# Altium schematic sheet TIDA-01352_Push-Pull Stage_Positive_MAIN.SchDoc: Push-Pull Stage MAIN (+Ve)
size 431 x 279 mm; Date: Not shown in title block; ApprovedBy: Not shown in title block; CheckedBy: Not shown in title block; Author: Not shown in title block; CompanyName: Not shown in title block; DrawnBy: Sanjay Pithadia; Engineer: Sanjay Pithadia; Organization: Not shown in title block; Address1: Not shown in title block; Address2: Not shown in title block; Address3: Not shown in title block; Address4: Not shown in title block; DocumentNumber: 1; Revision: Use project parameter SCH_Rev; SheetNumber: 2; SheetTotal: 9; PageSetup: Record=PageOptions¦CenterHorizontal=True¦CenterVertical=True¦PrintScale=1.00¦XCorrection=1.00¦YCorrection=1.00¦PrintKind=0¦BorderSize=5000000¦LeftOffset=0¦BottomOffset=0¦Orientation=2¦PaperLength=1000¦PaperWidth=1000¦Scale=100¦PaperSource=15¦PrintQuality=600¦MediaType=1¦DitherType=10¦PaperKind=Letter¦PrintScaleMode=1
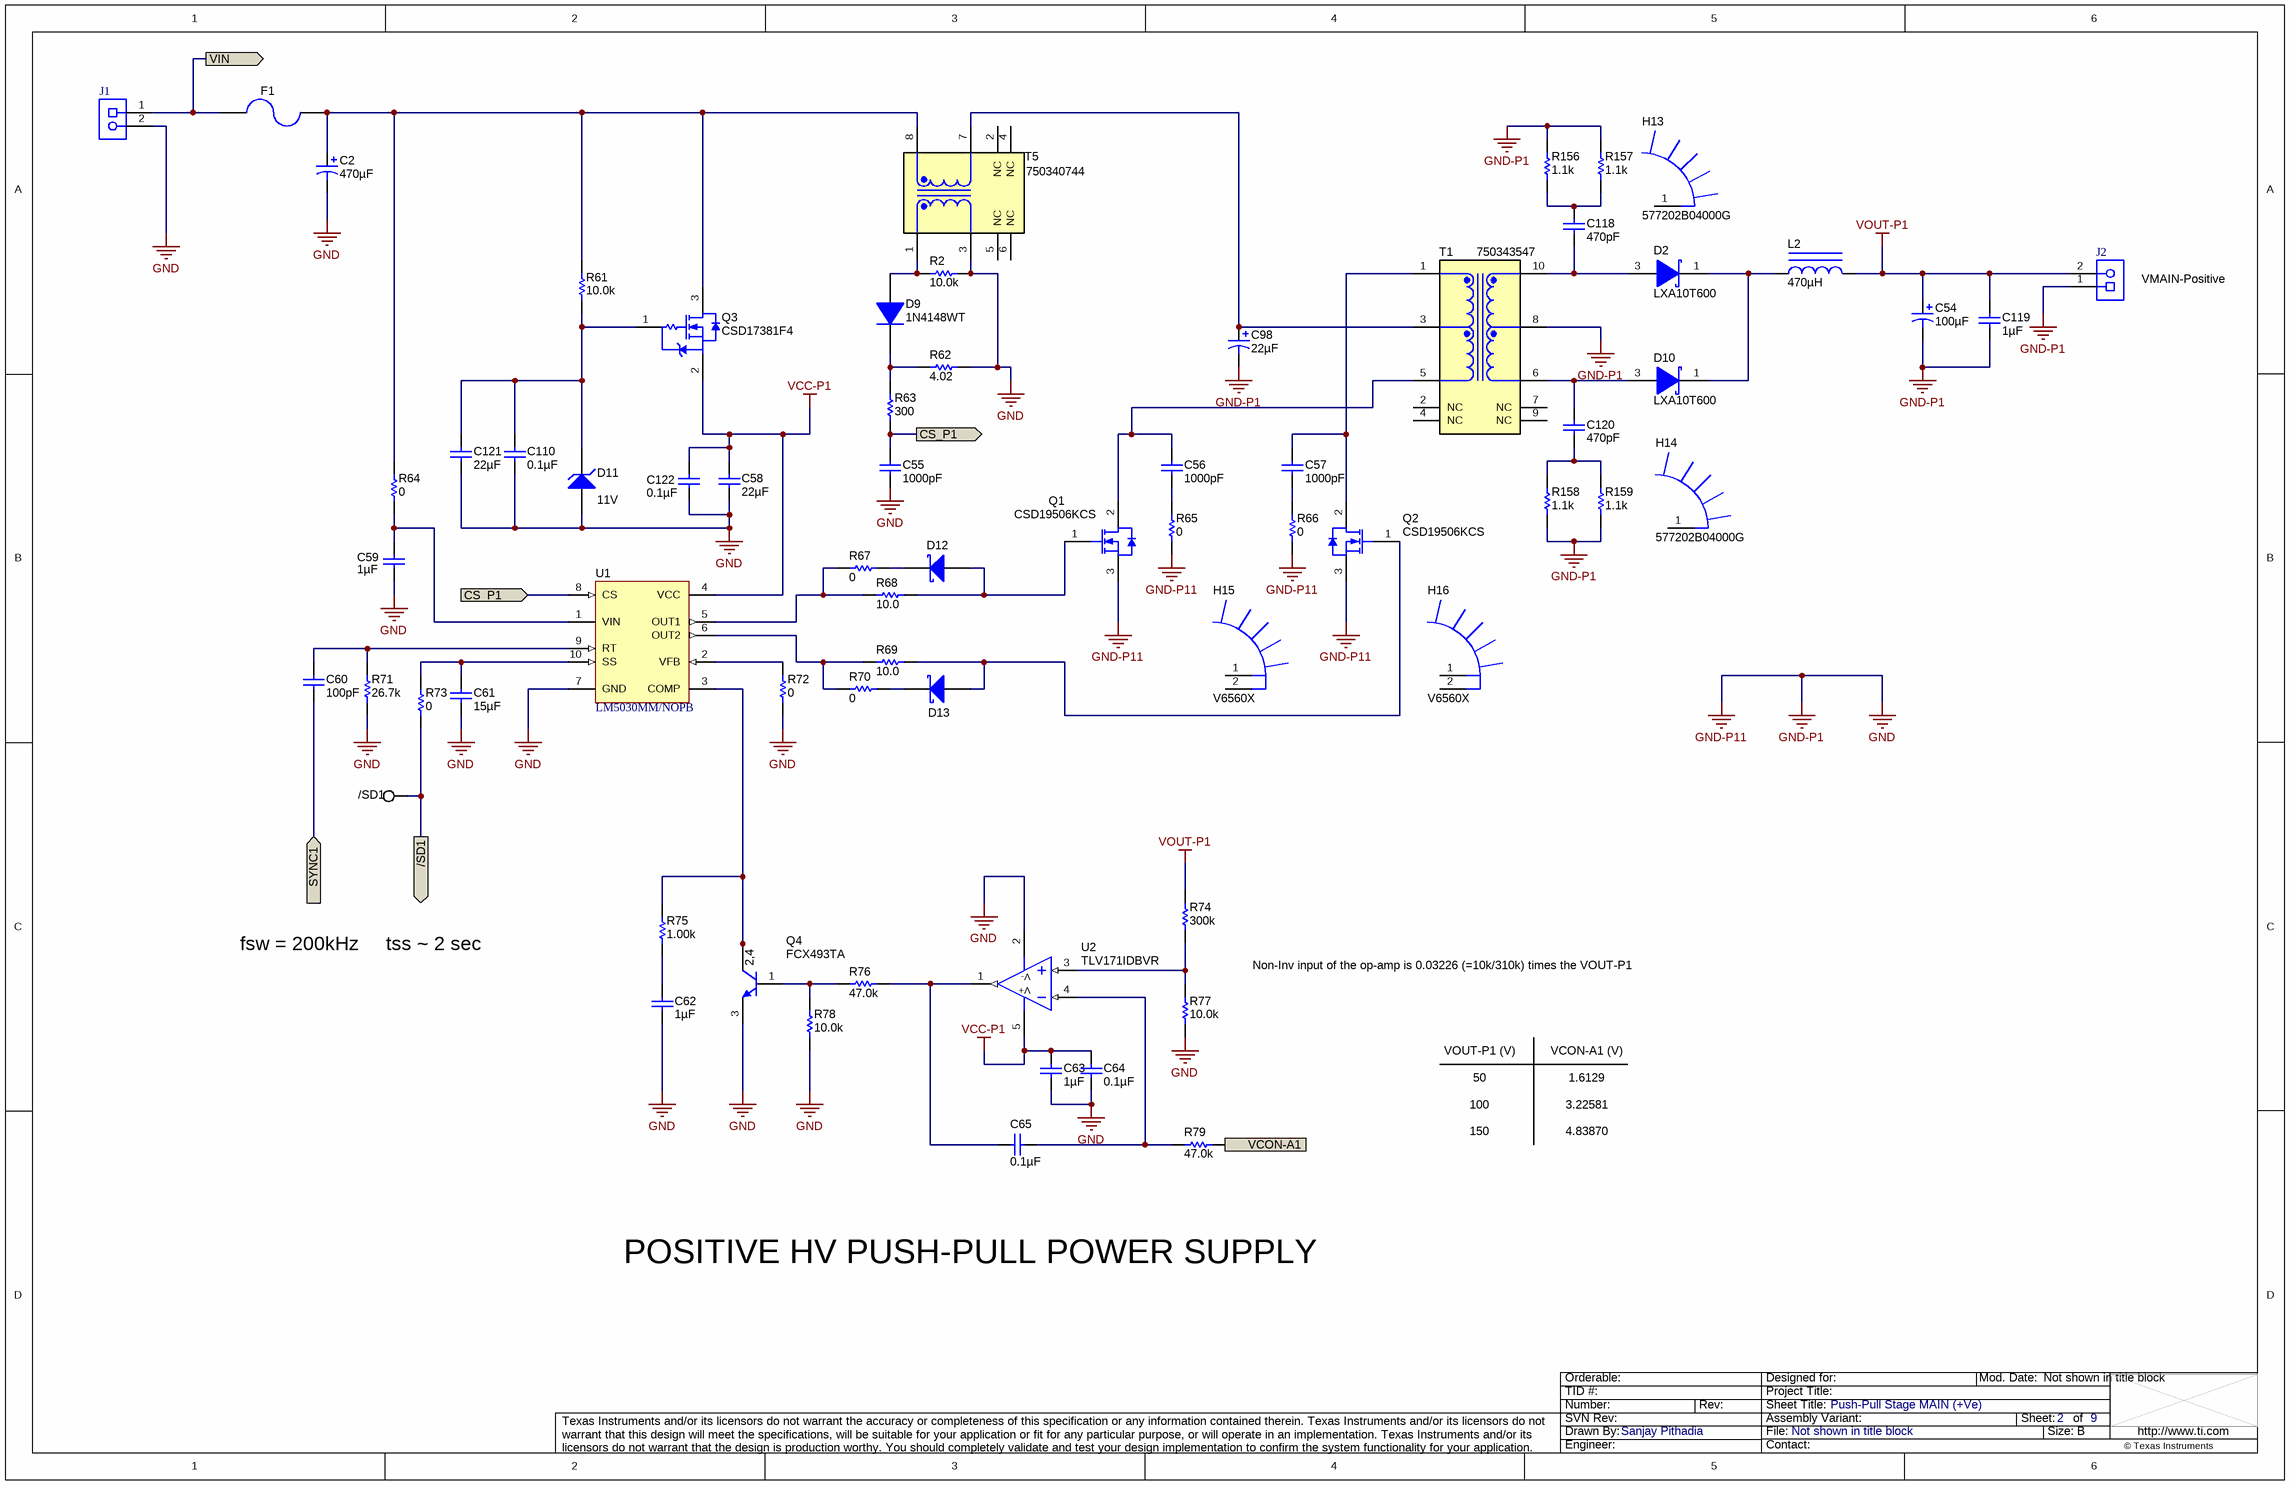
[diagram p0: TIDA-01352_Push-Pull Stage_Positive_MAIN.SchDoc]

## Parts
/SD1  5002  [Keystone5002]  (value not drawn)
C2  ValueDisplayed: 470µF  [WCAP-ATLI_1300x3000]  (hidden comment: 860080778023)
C54  ValueDisplayed: 100µF  [Nichicon_2000x3000_Snap]  (hidden comment: LLS2G101MELY)
C55  ValueDisplayed: 1000pF  [0603]  (hidden comment: GRM188R71E102KA01D)
C56  ValueDisplayed: 1000pF  [0603]  (hidden comment: GRM188R71E102KA01D)
C57  ValueDisplayed: 1000pF  [0603]  (hidden comment: GRM188R71E102KA01D)
C58  ValueDisplayed: 22µF  [1210_280]  (hidden comment: 12103D226MAT2A)
C59  ValueDisplayed: 1µF  [0805_HV]  (hidden comment: 08055C105KAT2A)
C60  ValueDisplayed: 100pF  [0603]  (hidden comment: 06035A101FAT2A)
C61  ValueDisplayed: 15µF  [0805_HV]  (hidden comment: C2012X5R1V156M125AC)
C62  ValueDisplayed: 1µF  [0603]  (hidden comment: GMK107BJ105KA-T)
C63  ValueDisplayed: 1µF  [0805_HV]  (hidden comment: 08055C105KAT2A)
C64  ValueDisplayed: 0.1µF  [0603]  (hidden comment: 06035C104KAT2A)
C65  ValueDisplayed: 0.1µF  [0603]  (hidden comment: 06035C104KAT2A)
C98  ValueDisplayed: 22µF  [SM_RADIAL_E]  (hidden comment: EEE-FC1H220P)
C110  ValueDisplayed: 0.1µF  [0603]  (hidden comment: 06035C104KAT2A)
C118  ValueDisplayed: 470pF  [1206]  (hidden comment: VJ1206Y471KBEAT4X)
C119  ValueDisplayed: 1µF  [2220_200]  (hidden comment: GRM55DR72E105KW01L)
C120  ValueDisplayed: 470pF  [1206]  (hidden comment: VJ1206Y471KBEAT4X)
C121  ValueDisplayed: 22µF  [1210_280]  (hidden comment: 12103D226MAT2A)
C122  ValueDisplayed: 0.1µF  [0603]  (hidden comment: 06035C104KAT2A)
D2  LXA10T600  [TO-220AC]
D9  1N4148WT  [Fairchild_SOD-523F]
D10  LXA10T600  [TO-220AC]
D11  value 11V  [SMA]  (hidden comment: 1SMA5926BT3G)
D12  PMEG1030EJ,115  [SOD-323F]  (value not drawn)
D13  PMEG1030EJ,115  [SOD-323F]  (value not drawn)
F1  0678L9150-02  [Fuse_0678L]  (value not drawn)
H13  577202B04000G  [Aavid_577202B04000G]
H14  577202B04000G  [Aavid_577202B04000G]
H15  V6560X  [ASMN_V6560X]
H16  V6560X  [ASMN_V6560X]
J1  OSTT7020150  [On-Shore_OSTT7020150]  (value not drawn)
J2  1727010  [PhoenixConact_1727010]  (value not drawn)
L2  ValueDisplayed: 470µH  [1447440C]  (hidden comment: 1447440C)
Q1  CSD19506KCS  [KCS0003B]
Q2  CSD19506KCS  [KCS0003B]
Q3  CSD17381F4  [YJC0003A]
Q4  FCX493TA  [SOT-89-3]
R2  ValueDisplayed: 10.0k  [0603]  (hidden comment: CRCW060310K0FKEA)
R61  ValueDisplayed: 10.0k  [0603]  (hidden comment: CRCW060310K0FKEA)
R62  ValueDisplayed: 4.02  [0805_HV]  (hidden comment: CRCW08054R02FKEA)
R63  ValueDisplayed: 300  [0603]  (hidden comment: RC0603FR-07300RL)
R64  ValueDisplayed: 0  [0603]  (hidden comment: CRCW06030000Z0EA)
R65  ValueDisplayed: 0  [0603]  (hidden comment: CRCW06030000Z0EA)
R66  ValueDisplayed: 0  [0603]  (hidden comment: CRCW06030000Z0EA)
R67  ValueDisplayed: 0  [0603]  (hidden comment: CRCW06030000Z0EA)
R68  ValueDisplayed: 10.0  [0603]  (hidden comment: CRCW060310R0FKEA)
R69  ValueDisplayed: 10.0  [0603]  (hidden comment: CRCW060310R0FKEA)
R70  ValueDisplayed: 0  [0603]  (hidden comment: CRCW06030000Z0EA)
R71  ValueDisplayed: 26.7k  [0603]  (hidden comment: CRCW060326K7FKEA)
R72  ValueDisplayed: 0  [0603]  (hidden comment: CRCW06030000Z0EA)
R73  ValueDisplayed: 0  [0603]  (hidden comment: CRCW06030000Z0EA)
R74  ValueDisplayed: 300k  [1206]  (hidden comment: RC1206FR-07300KL)
R75  ValueDisplayed: 1.00k  [0603]  (hidden comment: CRCW06031K00FKEA)
R76  ValueDisplayed: 47.0k  [0603]  (hidden comment: RC0603FR-0747KL)
R77  ValueDisplayed: 10.0k  [1206]  (hidden comment: CRCW120610K0FKEA)
R78  ValueDisplayed: 10.0k  [0603]  (hidden comment: CRCW060310K0FKEA)
R79  ValueDisplayed: 47.0k  [0603]  (hidden comment: RC0603FR-0747KL)
R156  ValueDisplayed: 1.1k  [PR01]  (hidden comment: PR01000101101JR500)
R157  ValueDisplayed: 1.1k  [PR01]  (hidden comment: PR01000101101JR500)
R158  ValueDisplayed: 1.1k  [PR01]  (hidden comment: PR01000101101JR500)
R159  ValueDisplayed: 1.1k  [PR01]  (hidden comment: PR01000101101JR500)
T1  750343547  [Wurth_750343473]
T5  750340744  [Wurth_750340744]
U1  LM5030MM/NOPB  [MUB10A_N]
U2  TLV171IDBVR  [DBV0005A_N]

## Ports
/SD1 (out), CS_P1 (in), CS_P1 (out), SYNC1 (in), VCON-A1 (in), VIN (out)

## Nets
GND: C2.2(-) C54.2(-) C55.2 C58.2 C59.2 C61.2 C62.2 C63.2 C64.2 C98.2(-) C110.2 C119.2 C121.2 C122.2 D11.2(A) J1.2 J2.1 Q1.3(S) Q2.3(S) Q4.3(E) R2.1 R62.2 R65.2 R66.2 R71.1 R72.1 R77.1 R78.1 R156.2 R157.2 R158.1 R159.1 T1.8 T5.3 U1.7(GND) U2.2(V-)  [also labelled GND-P1, GND-P11]
VCC-P1: C58.1 C63.1 C64.1 C122.1 Q3.2(S) U1.4(VCC) U2.5(V+)
VOUT-P1: C54.1(+) C119.1 J2.2 L2.2 R74.2
/SD1: /SD1.1 R73.1 ; port /SD1
CS_P1: C55.1 R63.1 U1.8(CS) ; port CS_P1
SYNC1: C60.2 ; port SYNC1
VCON-A1: R79.2 ; port VCON-A1
VIN: F1.2 J1.1 ; port VIN
NetC2_1: C2.1(+) F1.1 Q3.3(D) R61.2 R64.2 T5.8
NetC56_1: C56.1 Q1.2(D) T1.5
NetC56_2: C56.2 R65.1
NetC57_1: C57.1 Q2.2(D) T1.1
NetC57_2: C57.2 R66.1
NetC59_1: C59.1 R64.1 U1.1(VIN)
NetC60_1: C60.1 R71.2 U1.9(RT)
NetC61_1: C61.1 R73.2 U1.10(SS)
NetC62_1: C62.1 R75.1
NetC65_1: C65.1 R79.1 U2.4(IN-)
NetC65_2: C65.2 R76.2 U2.1(OUT)
NetC98_1: C98.1(+) T1.3 T5.7
NetC110_1: C110.1 C121.1 D11.1(K) Q3.1(G) R61.1
NetC118_1: C118.1 R156.1 R157.1
NetC118_2: C118.2 D2.3(K) T1.10
NetC120_1: C120.1 D10.3(K) T1.6
NetC120_2: C120.2 R158.2 R159.2
NetD2_1: D2.1(A) D10.1(A) L2.1
NetD9_1: D9.1(K) R62.1 R63.2
NetD9_2: D9.2(A) R2.2 T5.1
NetD12_1: D12.1(K) R67.1
NetD12_2: D12.2(A) Q1.1(G) R68.2
NetD13_1: D13.1(K) R70.1
NetD13_2: D13.2(A) Q2.1(G) R69.2
NetQ4_1: Q4.1(B) R76.1 R78.2
NetQ4_2: Q4.2(C) Q4.4(C) R75.2 U1.3(COMP)
NetR67_2: R67.2 R68.1 U1.5(OUT1)
NetR69_1: R69.1 R70.2 U1.6(OUT2)
NetR72_2: R72.2 U1.2(VFB)
NetR74_1: R74.1 R77.2 U2.3(IN+)

Not connected (* = marked no-connect by the designer): H13 1; H14 1; H15 1 2; H16 1 2; T1 2(NC) 4(NC) 7(NC) 9(NC); T5 2(NC) 4(NC) 5(NC) 6(NC)

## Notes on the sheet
- (near J2) VMAIN-Positive
- fsw = 200kHz
- tss ~ 2 sec
- Non-Inv input of the op-amp is 0.03226 (=10k/310k) times the VOUT-P1
- VOUT-P1 (V)
- 50
- 100
- VCON-A1 (V)
- 1.6129
- 3.22581
- 150
- 4.83870
- POSITIVE HV PUSH-PULL POWER SUPPLY

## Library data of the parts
/SD1 = 5002: Test Point, Miniature, White, TH; Manufacturer: Keystone; CompType: Test Point Loop; ContactFinish: Silver
C2 = 860080778023: CAP, AL, 470 µF, 63 V, +/- 20%, TH; Manufacturer: Wurth Elektronik; Polarized: Y; CompType: Capacitor; Value: 470uF; U/M: EA; Cap_F: 0.00047; Tolerance_%: 20; Value1: Unknown; VDC_V: 63; Value2: 63V; IRMS_A: 2.225; TaMin_C: -55; TaMax_C: 105; Cap_Case: 13x30mm; SizeAreaWB_mm2: 225; SizeArea_mm2: 169; SizeX_mm: 13; SizeZ_mm: 31.5; AEC Category: Q200; AEC Qualified: N
C54 = LLS2G101MELY: CAP, AL, 100 µF, 400 V, +/- 20%, TH; Manufacturer: Nichicon; Polarized: Y; CompType: Capacitor; Value: 100uF; U/M: EA; Cap_F: 0.0001; Tolerance_%: 20; Value1: Unknown; VDC_V: 400; Value2: 400V; IRMS_A: 0.95; TaMin_C: -25; TaMax_C: 85; Cap_Case: 20x30mm; SizeAreaWB_mm2: 484; SizeZ_mm: 32; AEC Category: Q200; AEC Qualified: N
C55-C57 = GRM188R71E102KA01D: CAP, CERM, 1000 pF, 25 V, +/- 10%, X7R, 0603; Manufacturer: MuRata; Polarized: N; CompType: Capacitor; Value: 1000pF; U/M: EA; Cap_F: 0.000000001; Tolerance_%: 10; Value1: Unknown; VDC_V: 25; Value2: 25V; TaMin_C: -55; TaMax_C: 125; SizeArea_mm2: 1.28; SizeAreaWB_mm2: 4.68; SizeX_mm: 1.6; SizeY_mm: 0.8; SizeZ_mm: 1; AEC Category: Q200
C58 C121 = 12103D226MAT2A: CAP, CERM, 22 µF, 25 V, +/- 20%, X5R, 1210; Manufacturer: AVX; Polarized: N; CompType: Capacitor; Value: 22uF; U/M: EA; Cap_F: 0.000022; Tolerance_%: 20; Value1: Unknown; VDC_V: 25; Value2: 25V; TaMin_C: -55; TaMax_C: 85; Cap_Case: 1210; SizeArea_mm2: 8; SizeAreaWB_mm2: 14.7; SizeX_mm: 3.2; SizeY_mm: 2.5; SizeZ_mm: 2.8; AEC Category: Q200
C59 C63 = 08055C105KAT2A: CAP, CERM, 1 µF, 50 V, +/- 10%, X7R, 0805; Manufacturer: AVX; Polarized: N; CompType: Capacitor; Value: 1uF; U/M: EA; Cap_F: 0.000001; Tolerance_%: 10; Value1: Unknown; VDC_V: 50; Value2: 50V; TaMin_C: -55; TaMax_C: 125; Cap_Case: 0805; SizeArea_mm2: 2.5; SizeAreaWB_mm2: 6.75; SizeX_mm: 2; SizeY_mm: 1.25; SizeZ_mm: 1.45; AEC Category: Q200
C60 = 06035A101FAT2A: CAP, CERM, 100 pF, 50 V, +/- 1%, C0G/NP0, 0603; Manufacturer: AVX; Polarized: N; CompType: Capacitor; Value: 100pF; U/M: EA; Cap_F: 0.0000000001; Tolerance_%: 1; Value1: Unknown; VDC_V: 50; Value2: 50V; TaMin_C: -55; TaMax_C: 125; SizeArea_mm2: 1.28; SizeAreaWB_mm2: 4.68; SizeX_mm: 1.6; SizeY_mm: 0.8; AEC Category: Q200
C61 = C2012X5R1V156M125AC: CAP, CERM, 15 µF, 35 V, +/- 20%, X5R, 0805; Manufacturer: TDK; Polarized: N; CompType: Capacitor; Value: 15uF; U/M: EA; Cap_F: 0.000015; Tolerance_%: 20; ESR_ohm: 0.001669; Value1: 0.001669 ohm; VDC_V: 35; Value2: 35V; IRMS_A: 5.04984; TaMin_C: -55; TaMax_C: 85; Cap_Case: 0805; SizeArea_mm2: 2.5; SizeAreaWB_mm2: 6.75; SizeX_mm: 2; SizeY_mm: 1.25; SizeZ_mm: 1.45; AEC Category: Q200
C62 = GMK107BJ105KA-T: CAP, CERM, 1 µF, 35 V, +/- 10%, X5R, 0603; Manufacturer: Taiyo Yuden; Polarized: N; CompType: Capacitor; Value: 1uF; U/M: EA; Cap_F: 0.000001; Tolerance_%: 10; Value1: Unknown; VDC_V: 35; Value2: 35V; TaMin_C: -55; TaMax_C: 85; SizeArea_mm2: 1.28; SizeAreaWB_mm2: 4.68; SizeX_mm: 1.6; SizeY_mm: 0.8; SizeZ_mm: 1; AEC Category: Q200
C64 C65 C110 C122 = 06035C104KAT2A: CAP, CERM, 0.1 µF, 50 V, +/- 10%, X7R, 0603; Manufacturer: AVX; Polarized: N; CompType: Capacitor; Value: 0.1uF; U/M: EA; Cap_F: 0.0000001; Tolerance_%: 10; Value1: Unknown; VDC_V: 50; Value2: 50V; TaMin_C: -55; TaMax_C: 125; SizeArea_mm2: 1.28; SizeAreaWB_mm2: 4.68; SizeX_mm: 1.6; SizeY_mm: 0.8; SizeZ_mm: 1; AEC Category: Q200
C98 = EEE-FC1H220P: CAP, AL, 22 µF, 50 V, +/- 20%, 0.7 ohm, SMD; Manufacturer: Panasonic; Polarized: Y; CompType: Capacitor; Value: 22uF; U/M: EA; Cap_F: 0.000022; Tolerance_%: 20; Value1: 0.7 ohm; VDC_V: 50; Value2: 50V; ESR_ohm: 0.7; IRMS_A: 0.12; TaMin_C: -40; TaMax_C: 105; Cap_Case: E; SizeAreaWB_mm2: 118.45; SizeArea_mm2: 78.85; SizeX_mm: 9.5; SizeY_mm: 8.3; SizeZ_mm: 6.2; AEC Category: Q200
C118 C120 = VJ1206Y471KBEAT4X: CAP, CERM, 470 pF, 500 V, +/- 10%, X7R, 1206; Manufacturer: Vishay-Vitramon; Polarized: N; CompType: Capacitor; Value: 470pF; U/M: EA; Cap_F: 0.00000000047; Tolerance_%: 10; Value1: Unknown; VDC_V: 500; Value2: 500V; TaMin_C: -55; TaMax_C: 125; SizeArea_mm2: 5.12; SizeAreaWB_mm2: 10.92; SizeX_mm: 3.2; SizeY_mm: 1.6; SizeZ_mm: 1.35; AEC Category: Q200
C119 = GRM55DR72E105KW01L: CAP, CERM, 1 µF, 250 V, +/- 10%, X7R, 2220; Manufacturer: MuRata; Polarized: N; CompType: Capacitor; Value: 1uF; U/M: EA; Cap_F: 0.000001; Tolerance_%: 10; ESR_ohm: 0.007086; Value1: 0.007086 ohm; VDC_V: 250; Value2: 250V; IRMS_A: 2.0605; TaMin_C: -55; TaMax_C: 125; Cap_Case: 2220; SizeArea_mm2: 28.5; SizeAreaWB_mm2: 53.9; SizeX_mm: 5.7; SizeY_mm: 5; SizeZ_mm: 2; AEC Category: Q200
D2 D10 = LXA10T600: Diode, Schottky, 600 V, 10 A, TH; Manufacturer: Power Integrations; SymbolCreator: a0412235; U/M: EA; Vf_V: 2.4; Value: 600V; Value1: 10A; Value2: 2.4V; Io_A: 10; Vr_V: 600; TJmax_C: 150; RJC_CperW: 1.4; SizeAreaWB_mm2: 78.975; SizeArea_mm2: 45.675; SizeX_mm: 10.15; SizeY_mm: 4.5; SizeZ_mm: 23; AEC Category: Q101; AEC Qualified: N
D9 = 1N4148WT: Diode, Switching, 75 V, 0.3 A, SOD-523F; Manufacturer: Fairchild Semiconductor; U/M: EA; Value: 75V; Value1: 0.3A; Io_A: 0.3; Vr_V: 75; TJmax_C: 150; SizeAreaWB_mm2: 4.68; SizeArea_mm2: 1.28; SizeX_mm: 1.6; SizeY_mm: 0.8; SizeZ_mm: 0.7; AEC Category: Q101
D11 = 1SMA5926BT3G: Diode, Zener, 11 V, 1.5 W, SMA; Manufacturer: ON Semiconductor; SymbolCreator: a0412235; U/M: EA; Power_W: 1.5; Vz_V: 11; Value1: 1.5W; RJA_CperW: 250; SizeAreaWB_mm2: 37.3428; SizeArea_mm2: 16.3228; SizeX_mm: 5.59; SizeY_mm: 2.92; SizeZ_mm: 2.87; AEC Category: Q101
D12 D13 = PMEG1030EJ,115: Diode, Schottky, 10 V, 3 A, SOD-323F; Manufacturer: NXP Semiconductor; U/M: EA; Vf_V: 0.53; Value: 10V; Value1: 3A; Value2: 0.53V; Io_A: 3; Vr_V: 10; TJmax_C: 150; SizeAreaWB_mm2: 7.875; SizeArea_mm2: 3.125; SizeX_mm: 2.5; SizeY_mm: 1.25; SizeZ_mm: 0.8; AEC Category: Q101; AEC Qualified: N
F1 = 0678L9150-02: Fuse, 15 A, 250 VAC, 72 VDC, SMD; Manufacturer: Bel Fuse; SizeAreaWB_mm2: 59.59; SizeArea_mm2: 29.89; SizeX_mm: 9.8; SizeY_mm: 3.05; SizeZ_mm: 3.18; VDC_V: 72; VAC_V: 250; Irating_A: 15; Rtyp_Ohm: 0.0036; MeltingTyp: 110
H13 H14 = 577202B04000G: HEATSINK TO-220 .500" COMPACT; Manufacturer: Aavid; SymbolCreator: a0412235
H15 H16 = V6560X: HEATSINK, ALUM, ANOD, for TO-220; Manufacturer: Assman WSW; SymbolCreator: a0799628
J1 = OSTT7020150: Terminal Block, 6.35mm, 2x1, TH; Manufacturer: On-Shore Technology; SymbolCreator: a0412235; Pitch_mm: 6.35; Gender: Female; Row_Count: 1; Current_A: 30; Voltage_V: 300; Cert_UL: Y
J2 = 1727010: Conn Term Block, 2POS, 3.81mm, TH; Manufacturer: Phoenix Contact; SymbolCreator: a0412235; CompType: Terminal Block
L2 = 1447440C: Inductor, Wirewound, 470 µH, 4 A, 0.125 ohm, TH; Manufacturer: MuRata; Value: 470uH; Ind_H: 470.0E-6; Imax_A: 4; Irms: 4A @ 50C rise; Isat: 4A @ 40% inductance drop; DCR_ohm: 0.125; Value2: 4A; SizeAreaWB_mm2: 1071.66; SizeArea_mm2: 944.66; SizeX_mm: 31.7; SizeY_mm: 29.8; SizeZ_mm: 23.5; AEC Category: Q200; AEC Qualified: N
Q1 Q2 = CSD19506KCS: MOSFET, N-CH, 80 V, 100 A, KCS0003B (TO-220-3); Manufacturer: Texas Instruments; Alternate Manufacturer: None; U/M: EA; ChType: N; Value: 80V; VdsMax_V: 80; Value1: ? ohm; Value2: 120 nC; QgTyp_nC: 120; Vgs_V: 20; IdsMax_A: 100; SizeAreaWB_mm2: 79.648; SizeArea_mm2: 46.228; SizeX_mm: 4.55; SizeY_mm: 10.16; SizeZ_mm: 20.45; AEC Category: Q101
Q3 = CSD17381F4: MOSFET, N-CH, 30 V, 3.1 A, YJC0003A (PICOSTAR-3); Manufacturer: Texas Instruments; Alternate Manufacturer: None; SymbolCreator: a0411947; U/M: EA; ChType: N; Value: 30V; VdsMax_V: 30; Value1: 0.09 ohm; Rdson45_ohm: 0.09; Value2: 1.04 nC; QgTyp_nC: 1.04; Vgs_V: 12; IdsMax_A: 3.1; SizeAreaWB_mm2: 3.327225; SizeArea_mm2: 0.657225; SizeX_mm: 1.035; SizeY_mm: 0.635; SizeZ_mm: 0.35; AEC Category: Q101
Q4 = FCX493TA, Diodes Inc.: Transistor, NPN, 100 V, 1 A, SOT-89; SymbolCreator: a0412235; PNP: 0; NPN: 1; Vceo_V: 100; Vcesat1_V: 0.6; Value: 100 V; Value1: 1 A; HfeMax: 300; TaMin_C: -65; TaMax_C: 150; CompType: BJT; U/M: EA; AEC Category: Q101; SizeAreaWB_mm2: 28.05; SizeArea_mm2: 18.45; SizeX_mm: 4.1; SizeY_mm: 4.5; SizeZ_mm: 1.5
R2 R61 R78 = CRCW060310K0FKEA: RES, 10.0 k, 1%, 0.1 W, 0603; Manufacturer: Vishay-Dale; CompType: Resistor; Value: 10.0k; Res_ohm: 10000; Value_Code: 10k0; Tolerance_%: 1; Power_W: 0.1; Value2: 0.1W; VDC_V: 75; TempCo: 100 ppm/C; SizeArea_mm2: 1.28; SizeX_mm: 1.6; SizeY_mm: 0.8; EIA_Code: E96; U/M: EA; AEC Category: Q200
R62 = CRCW08054R02FKEA: RES, 4.02, 1%, 0.125 W, 0805; Manufacturer: Vishay-Dale; CompType: Resistor; Value: 4.02; Value_Code: 4R02; Tolerance_%: 1; Power_W: 0.125; Value2: 0.125W; VDC_V: 150; TempCo: 100 ppm/C; SizeArea_mm2: 2.5; SizeX_mm: 2; SizeY_mm: 1.25; SizeZ_mm: 1.45; EIA_Code: E96; U/M: EA; AEC Category: Q200
R63 = RC0603FR-07300RL: RES, 300, 1%, 0.1 W, 0603; Manufacturer: Yageo America; CompType: Resistor; Value: 300; Value_Code: 300R; Tolerance_%: 1; Power_W: 0.1; Value2: 0.1W; VDC_V: 150; TempCo: 200 ppm/C; SizeArea_mm2: 1.28; SizeX_mm: 1.6; SizeY_mm: 0.8; U/M: EA; AEC Category: Q200
R64-R67 R70 R72 R73 = CRCW06030000Z0EA: RES, 0, 5%, 0.1 W, 0603; Manufacturer: Vishay-Dale; CompType: Resistor; Value: 0; Value_Code: 0000; Tolerance_%: 5; Power_W: 0.1; Value2: 0.1W; VDC_V: 75; TempCo: 200 ppm/C; SizeArea_mm2: 1.28; SizeX_mm: 1.6; SizeY_mm: 0.8; SizeZ_mm: 1; EIA_Code: E24; U/M: EA; AEC Category: Q200
R68 R69 = CRCW060310R0FKEA: RES, 10.0, 1%, 0.1 W, 0603; Manufacturer: Vishay-Dale; CompType: Resistor; Value: 10.0; Res_ohm: 10; Value_Code: 10R0; Tolerance_%: 1; Power_W: 0.1; Value2: 0.1W; VDC_V: 75; TempCo: 100 ppm/C; SizeArea_mm2: 1.28; SizeX_mm: 1.6; SizeY_mm: 0.8; EIA_Code: E96; U/M: EA; AEC Category: Q200
R71 = CRCW060326K7FKEA: RES, 26.7 k, 1%, 0.1 W, 0603; Manufacturer: Vishay-Dale; CompType: Resistor; Value: 26.7k; Res_ohm: 26700; Value_Code: 26k7; Tolerance_%: 1; Power_W: 0.1; Value2: 0.1W; VDC_V: 75; TempCo: 100 ppm/C; SizeArea_mm2: 1.28; SizeX_mm: 1.6; SizeY_mm: 0.8; EIA_Code: E96; U/M: EA; AEC Category: Q200
R74 = RC1206FR-07300KL: RES, 300 k, 1%, 0.25 W, 1206; Manufacturer: Yageo America; CompType: Resistor; Value: 300k; Res_ohm: 300000; Tolerance_%: 1; Power_W: 0.25; Value2: 0.25W; VDC_V: 200; TempCo: 100 ppm/C; SizeArea_mm2: 5.12; SizeX_mm: 3.2; SizeY_mm: 1.6; SizeZ_mm: 1.35; U/M: EA; AEC Category: Q200
R75 = CRCW06031K00FKEA: RES, 1.00 k, 1%, 0.1 W, 0603; Manufacturer: Vishay-Dale; CompType: Resistor; Value: 1.00k; Res_ohm: 1000; Value_Code: 1k00; Tolerance_%: 1; Power_W: 0.1; Value2: 0.1W; VDC_V: 75; TempCo: 100 ppm/C; SizeArea_mm2: 1.28; SizeX_mm: 1.6; SizeY_mm: 0.8; EIA_Code: E96; U/M: EA; AEC Category: Q200
R76 R79 = RC0603FR-0747KL: RES, 47.0 k, 1%, 0.1 W, 0603; Manufacturer: Yageo America; CompType: Resistor; Value: 47.0k; Res_ohm: 47000; Value_Code: 47k0; Tolerance_%: 1; Power_W: 0.1; Value2: 0.1W; VDC_V: 150; TempCo: 200 ppm/C; SizeArea_mm2: 1.28; SizeX_mm: 1.6; SizeY_mm: 0.8; U/M: EA; AEC Category: Q200
R77 = CRCW120610K0FKEA: RES, 10.0 k, 1%, 0.25 W, 1206; Manufacturer: Vishay-Dale; CompType: Resistor; Value: 10.0k; Res_ohm: 10000; Value_Code: 10k0; Tolerance_%: 1; Power_W: 0.25; Value2: 0.25W; VDC_V: 200; TempCo: 100 ppm/C; SizeArea_mm2: 5.12; SizeX_mm: 3.2; SizeY_mm: 1.6; SizeZ_mm: 1.35; EIA_Code: E96; U/M: EA; AEC Category: Q200; Green_Lifecycle: Active; Green_REACh: Passed
R156-R159 = PR01000101101JR500: RES, 1.1 k, 5%, 1 W, AEC-Q200 Grade 0, D2.5xL6.5mm; Manufacturer: Vishay-Bccomponents; CompType: Resistor; Value: 1.1k; Res_ohm: 1100; Value_Code: 1k10; Tolerance_%: 5; Power_W: 1; Value2: 1W; VDC_V: 350; TempCo: 250 ppm/C; EIA_Code: E24; U/M: EA; AEC Category: Q200; AEC Qualified: Y; AEC Grade: 0
T1 = 750343547: Transformer, 100 uH, TH; Manufacturer: Wurth Elektronik; SymbolCreator: Altium; ValueDisplayed: 100µH; Value: 100uH; DCR_ohm: 0.025; Lp: 100; Ind_H: 0.0001; Ns1toNp: 7.5; Rsec1_ohm: 0.27; Rsec2_ohm: 0.37; SizeAreaWB_mm2: 934.4274; SizeArea_mm2: 816.1274; SizeX_mm: 29.21; SizeY_mm: 27.94; SizeZ_mm: 21.59
T5 = 750340744: Transformer, TH; Manufacturer: Wurth Elektronik; SymbolCreator: Altium; ValueDisplayed: 2mH; Value: 2mH; Lp: 2000; Ns1toNp: 100; Rs1: 5.87; SizeAreaWB_mm2: 94.9181; SizeArea_mm2: 59.9181; SizeX_mm: 8.13; SizeY_mm: 7.37; SizeZ_mm: 5.46
U1 = LM5030MM/NOPB: 100V Push-Pull Current Mode PWM Controller, 10-pin MSOP, Pb-Free; Manufacturer: Texas Instruments; PackageTopMarking: ZXTT*S73B; PowerWise: Y; CompType: Switcher
U2 = TLV171IDBVR: 36-V, Single-Supply, Low-Power Operational Amplifiers for Cost-Sensitive Systems, DBV0005A (SOT-5); Alternate PartNumber: TLV171IDBVT; Manufacturer: Texas Instruments; SizeArea_mm2: 8.12; SizeAreaWB_mm2: 14.82; SizeX_mm: 2.8; SizeY_mm: 2.9; SizeZ_mm: 1.45; CompType: IC; U/M: EA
